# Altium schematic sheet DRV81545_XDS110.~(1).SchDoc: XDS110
size 431 x 279 mm; Date: Not shown in title block; ApprovedBy: Not shown in title block; CheckedBy: Not shown in title block; Author: Not shown in title block; CompanyName: Not shown in title block; DrawnBy: Mojtaba Afshar; Engineer: Not shown in title block; Organization: Not shown in title block; Address1: Not shown in title block; Address2: Not shown in title block; Address3: Not shown in title block; Address4: Not shown in title block; DocumentNumber: 2; Revision: Use project parameter SCH_Rev; SheetNumber: 1; SheetTotal: 5; PageSetup: Record=PageOptions¦CenterHorizontal=True¦CenterVertical=True¦PrintScale=1.00¦XCorrection=1.00¦YCorrection=1.00¦PrintKind=0¦BorderSize=5000000¦LeftOffset=0¦BottomOffset=0¦Orientation=2¦PaperLength=1000¦PaperWidth=1000¦Scale=100¦PaperSource=15¦PrintQuality=600¦MediaType=1¦DitherType=10¦PaperKind=Letter¦PrintScaleMode=1
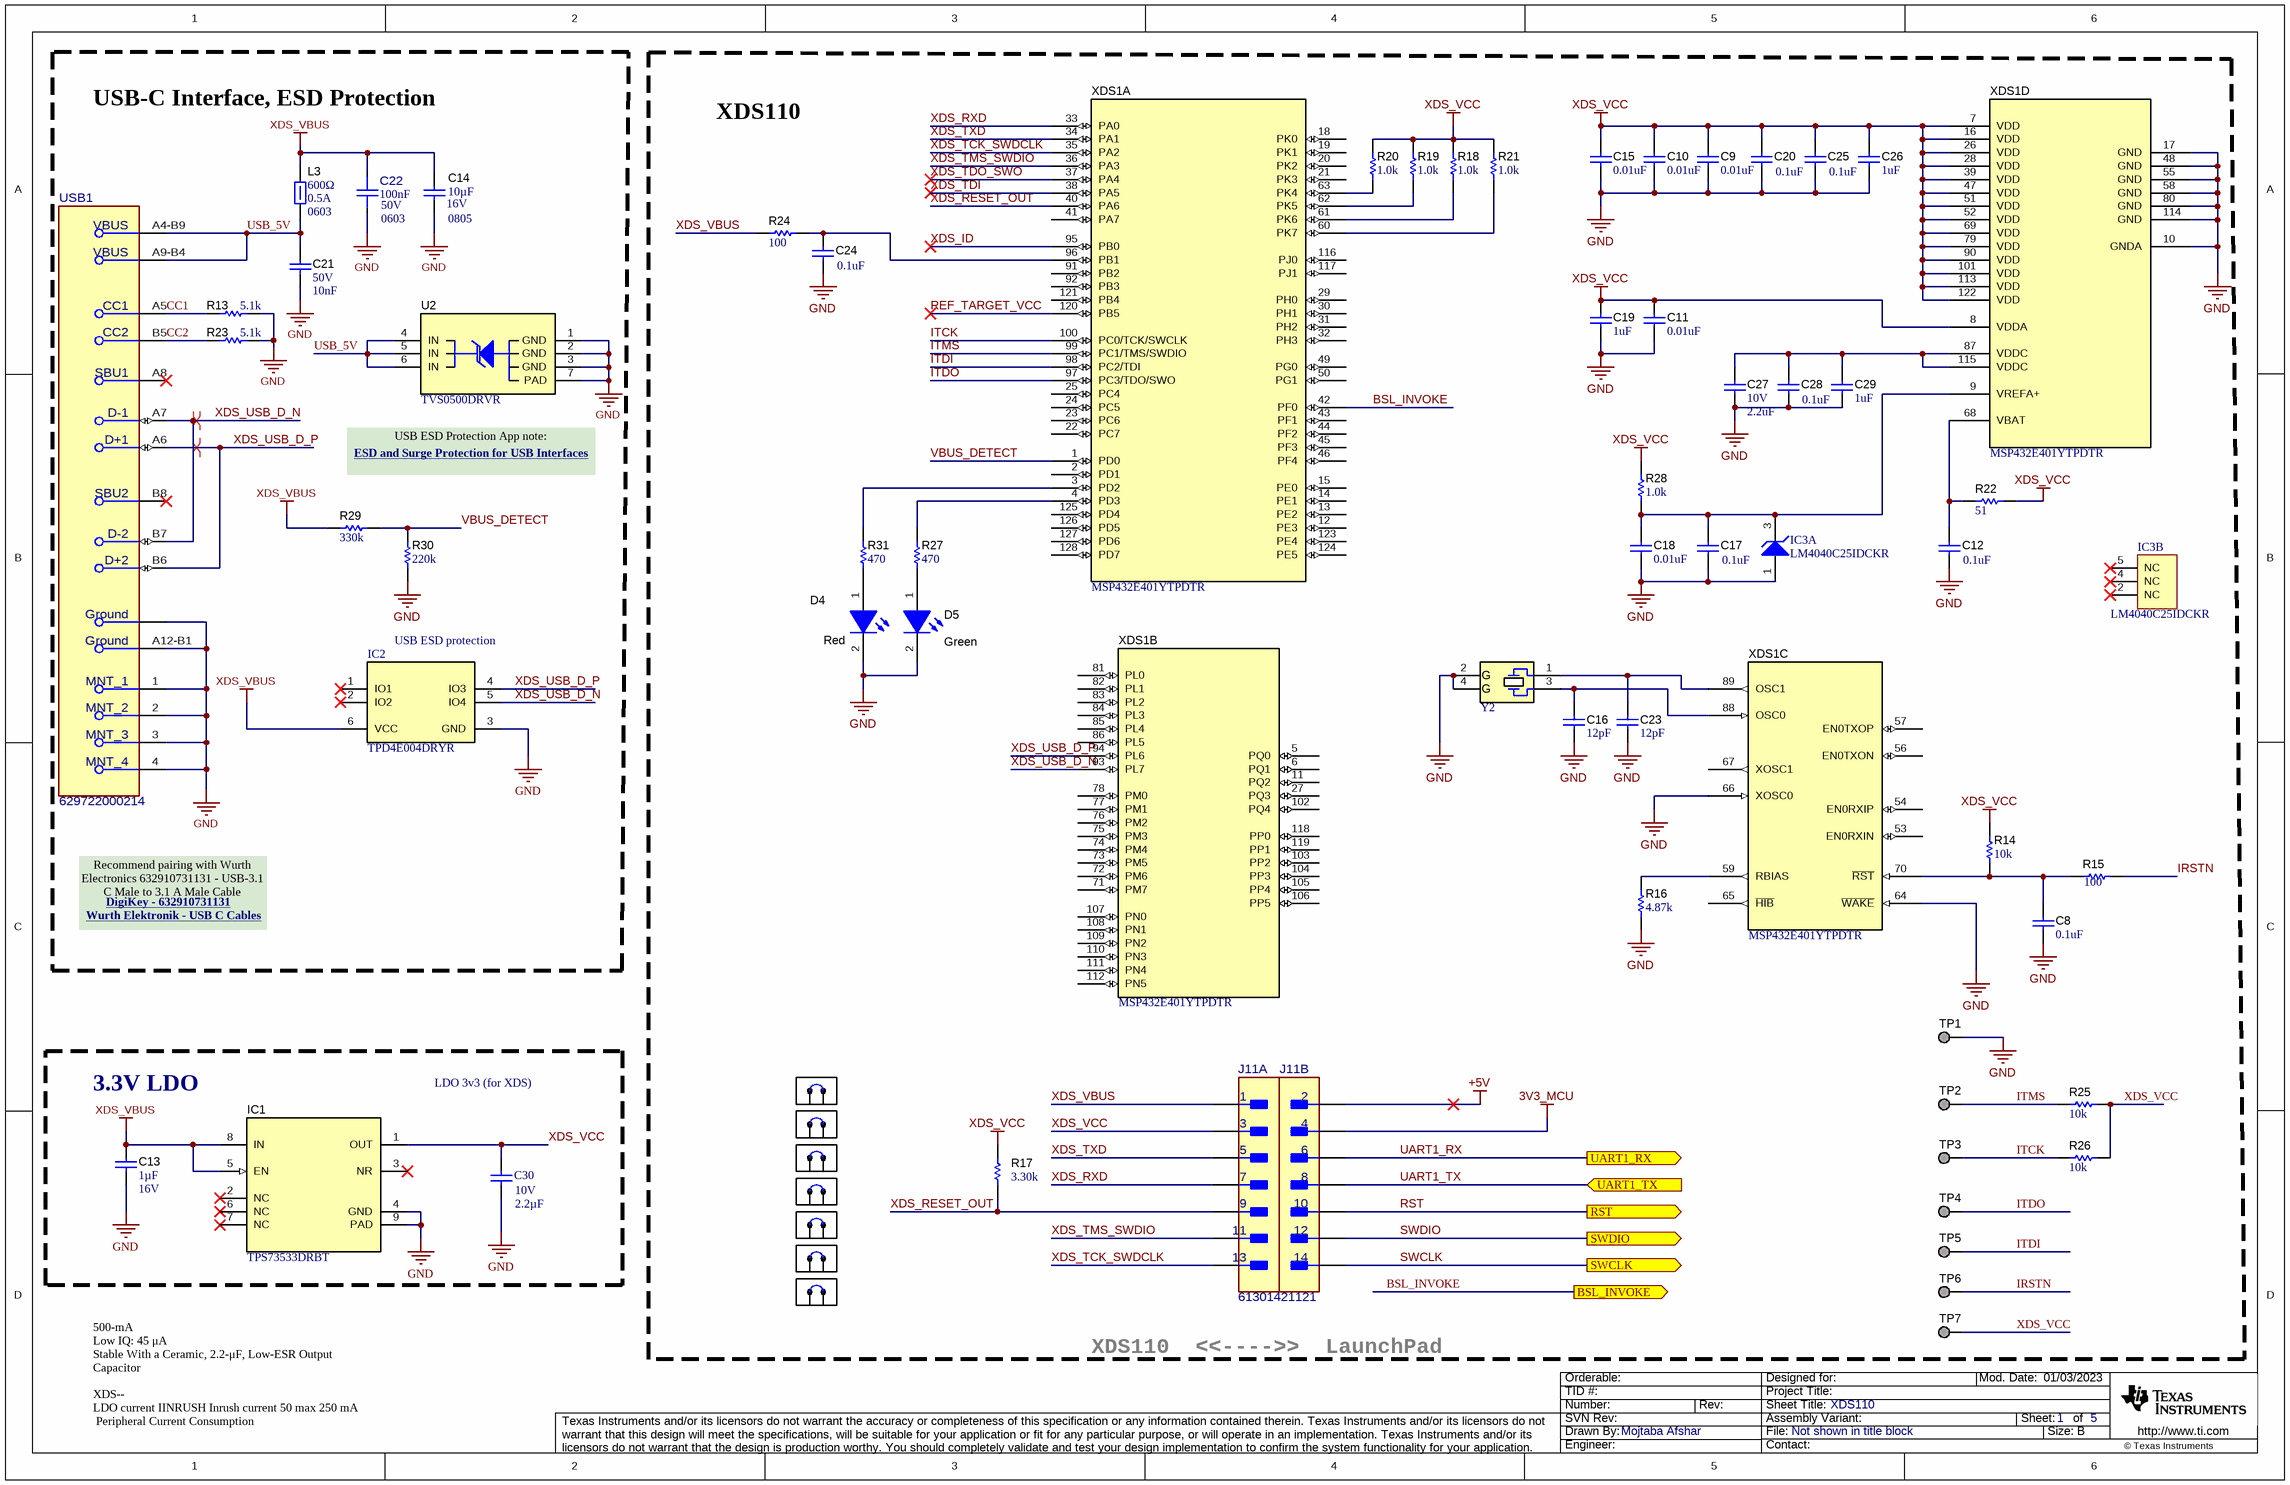
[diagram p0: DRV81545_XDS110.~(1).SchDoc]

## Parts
C8  ValueDisplayed: 0.1uF  [0402]  (hidden comment: GRM155R70J104KA01D)
C9  ValueDisplayed: 0.01uF  [0402]  (hidden comment: GRM155R71E103KA01D)
C10  ValueDisplayed: 0.01uF  [0402]  (hidden comment: GRM155R71E103KA01D)
C11  ValueDisplayed: 0.01uF  [0402]  (hidden comment: GRM155R71E103KA01D)
C12  ValueDisplayed: 0.1uF  [0402]  (hidden comment: GRM155R70J104KA01D)
C13  Cap_F: 1µF  VDC_V: 16V  [0603]  (hidden comment: 885012206052)
C14  PackageReference: 0805  VDC_V: 16V  ValueDisplayed: 10µF  [0805_150]  (hidden comment: 885012107014)
C15  ValueDisplayed: 0.01uF  [0402]  (hidden comment: GRM155R71E103KA01D)
C16  ValueDisplayed: 12pF  [0402]  (hidden comment: GRM1555C1H120JA01D)
C17  ValueDisplayed: 0.1uF  [0402]  (hidden comment: GRM155R70J104KA01D)
C18  ValueDisplayed: 0.01uF  [0402]  (hidden comment: GRM155R71E103KA01D)
C19  ValueDisplayed: 1uF  [0402]  (hidden comment: C1005X5R1E105K050BC)
C20  ValueDisplayed: 0.1uF  [0402]  (hidden comment: GRM155R70J104KA01D)
C21  VDC_V: 50V  Cap_F: 10nF  [0603]  (hidden comment: 885012206089)
C22  Cap_F: 100nF  PackageReference: 0603  VDC_V: 50V  [FP-885012206095_0603-MFG]  (hidden comment: 885012206095)
C23  ValueDisplayed: 12pF  [0402]  (hidden comment: GRM1555C1H120JA01D)
C24  ValueDisplayed: 0.1uF  [0402]  (hidden comment: GRM155R70J104KA01D)
C25  ValueDisplayed: 0.1uF  [0402]  (hidden comment: GRM155R70J104KA01D)
C26  ValueDisplayed: 1uF  [0402]  (hidden comment: C1005X5R1E105K050BC)
C27  VDC_V: 10V  ValueDisplayed: 2.2uF  [0603]  (hidden comment: C0603C225K8PACTU)
C28  ValueDisplayed: 0.1uF  [0402]  (hidden comment: GRM155R70J104KA01D)
C29  ValueDisplayed: 1uF  [0402]  (hidden comment: C1005X5R1E105K050BC)
C30  value 2.2µF  Rated Voltage (DC): 10V  [WCAP-CSGP_0603_L1.6W0.8H0.8_Reflow]  (hidden comment: 885012206027)
D4  value Red  [LED_LTST-C190_Red]  (hidden comment: LTST-C190KRKT)
D5  value Green  [LED_LTST-C190]  (hidden comment: LTST-C190GKT)
IC1  TPS73533DRBT  [DRB0008A]
IC2  TPD4E004DRYR  [DRY0006A]
IC3  LM4040C25IDCKR  [DCK0005A_N]  (parts A,B of 2)
J11  61301421121  [FP-61301421121_HDR14-MFG]  (parts A,B of 2)
L3  Value2: 0.5A  ValueDisplayed: 600Ω  [0603]  (hidden comment: 742863160)
R13  ValueDisplayed: 5.1k  [0603]  (hidden comment: RC0603JR-075K1L)
R14  ValueDisplayed: 10k  [0402]  (hidden comment: CRCW040210K0JNED)
R15  ValueDisplayed: 100  [0402]  (hidden comment: CRCW0402100RJNED)
R16  ValueDisplayed: 4.87k  [0402]  (hidden comment: CRCW04024K87FKED)
R17  ValueDisplayed: 3.30k  [0402]  (hidden comment: ERJ-2RKF3301X)
R18  ValueDisplayed: 1.0k  [0402]  (hidden comment: CRCW04021K00JNED)
R19  ValueDisplayed: 1.0k  [0402]  (hidden comment: CRCW04021K00JNED)
R20  ValueDisplayed: 1.0k  [0402]  (hidden comment: CRCW04021K00JNED)
R21  ValueDisplayed: 1.0k  [0402]  (hidden comment: CRCW04021K00JNED)
R22  ValueDisplayed: 51  [0402]  (hidden comment: CRCW040251R0JNED)
R23  ValueDisplayed: 5.1k  [0603]  (hidden comment: RC0603JR-075K1L)
R24  ValueDisplayed: 100  [0402]  (hidden comment: CRCW0402100RJNED)
R25  ValueDisplayed: 10k  [0402]  (hidden comment: CRCW040210K0JNED)
R26  ValueDisplayed: 10k  [0402]  (hidden comment: CRCW040210K0JNED)
R27  ValueDisplayed: 470  [0402]  (hidden comment: CRCW0402470RJNED)
R28  ValueDisplayed: 1.0k  [0402]  (hidden comment: CRCW04021K00JNED)
R29  ValueDisplayed: 330k  [0402]  (hidden comment: RC0402FR-07330KL)
R30  ValueDisplayed: 220k  [0402]  (hidden comment: RC0402FR-07220KL)
R31  ValueDisplayed: 470  [0402]  (hidden comment: CRCW0402470RJNED)
SH-J14  60900213421  [Wurth_60900213421]  (value not drawn)
SH-J15  60900213421  [Wurth_60900213421]  (value not drawn)
SH-J16  60900213421  [Wurth_60900213421]  (value not drawn)
SH-J17  60900213421  [Wurth_60900213421]  (value not drawn)
SH-J18  60900213421  [Wurth_60900213421]  (value not drawn)
SH-J19  60900213421  [Wurth_60900213421]  (value not drawn)
SH-J20  60900213421  [Wurth_60900213421]  (value not drawn)
TP1  TESTPOINT  [TP_SM_1MM]  (value not drawn)  (no BOM)
TP2  TESTPOINT  [TP_SM_1MM]  (value not drawn)  (no BOM)
TP3  TESTPOINT  [TP_SM_1MM]  (value not drawn)  (no BOM)
TP4  TESTPOINT  [TP_SM_1MM]  (value not drawn)  (no BOM)
TP5  TESTPOINT  [TP_SM_1MM]  (value not drawn)  (no BOM)
TP6  TESTPOINT  [TP_SM_1MM]  (value not drawn)  (no BOM)
TP7  TESTPOINT  [TP_SM_1MM]  (value not drawn)  (no BOM)
U2  TVS0500DRVR  [DRV0006A]
USB1  629722000214  [FP-629722000214_CONN_USB-MFG]
XDS1  MSP432E401YTPDTR  [PDT0128A]  (parts A,B,C,D of 4)
Y2  NX3225GA-16.000M-STD-CRG-1  [NDK_NX3225GA]  (value not drawn)

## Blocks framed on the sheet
USB-C Interface, ESD Protection: C14 C21 C22 IC2 L3 R13 R23 R29 R30 U2 USB1
XDS110: C8-C12 C15-C20 C23-C29 D4 D5 IC3 J11 R14-R22 R24-R28 R31 SH-J14-SH-J20 TP1-TP7 XDS1 Y2
3.3V LDO: C13 C30 IC1

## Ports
BSL_INVOKE (out), RST (out), SWCLK (out), SWDIO (out), UART1_RX (out), UART1_TX (in)

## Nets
3V3_MCU: J11.4
+5V: J11.2
GND: C8.2 C9.2 C10.2 C11.2 C12.2 C13.2 C14.2 C15.2 C16.2 C17.2 C18.2 C19.2 C20.2 C21.2 C22.2 C23.2 C24.2 C25.2 C26.2 C27.2 C28.2 C29.2 C30.1 D4.2(K) D5.2(K) IC1.4(GND) IC1.9(PAD) IC2.3(GND) IC3.1(ANODE) R13.2 R16.1 R23.2 R30.1 TP1.1 U2.1(GND) U2.2(GND) U2.3(GND) U2.7(PAD) USB1.1(MNT_1) USB1.2(MNT_2) USB1.3(MNT_3) USB1.4(MNT_4) USB1.A1-B12(Ground) USB1.A12-B1(Ground) XDS1.10(GNDA) XDS1.17(GND) XDS1.48(GND) XDS1.55(GND) XDS1.58(GND) XDS1.64(~{WAKE}) XDS1.66(XOSC0) XDS1.80(GND) XDS1.114(GND) Y2.2(GND) Y2.4(GND)
XDS_VBUS: C13.1 C14.1 C22.1 IC1.5(EN) IC1.8(IN) IC2.6(VCC) J11.1 L3.2 R24.1 R29.1
XDS_VCC: C9.1 C10.1 C11.1 C15.1 C19.1 C20.1 C25.1 C26.1 C30.2 IC1.1(OUT) J11.3 R14.2 R17.2 R18.2 R19.2 R20.2 R21.2 R22.2 R25.1 R26.1 R28.2 TP7.1 XDS1.7(VDD) XDS1.8(VDDA) XDS1.16(VDD) XDS1.26(VDD) XDS1.28(VDD) XDS1.39(VDD) XDS1.47(VDD) XDS1.51(VDD) XDS1.52(VDD) XDS1.69(VDD) XDS1.79(VDD) XDS1.90(VDD) XDS1.101(VDD) XDS1.113(VDD) XDS1.122(VDD)
BSL_INVOKE: XDS1.42(PF0) ; port BSL_INVOKE
CC1: R13.1 USB1.A5(CC1)
CC2: R23.1 USB1.B5(CC2)
IRSTN: R15.1 TP6.1
ITCK: R26.2 TP3.1 XDS1.100(PC0/TCK/SWCLK)
ITDI: TP5.1 XDS1.98(PC2/TDI)
ITDO: TP4.1 XDS1.97(PC3/TDO/SWO)
ITMS: R25.2 TP2.1 XDS1.99(PC1/TMS/SWDIO)
REF_TARGET_VCC: XDS1.120(PB5)
RST: J11.10 ; port RST
SWCLK: J11.14 ; port SWCLK
SWDIO: J11.12 ; port SWDIO
UART1_RX: J11.6 ; port UART1_RX
UART1_TX: J11.8 ; port UART1_TX
USB_5V: C21.1 L3.1 U2.4(IN) U2.5(IN) U2.6(IN) USB1.A4-B9(VBUS) USB1.A9-B4(VBUS)
VBUS_DETECT: R29.2 R30.2 XDS1.1(PD0)
XDS_ID: XDS1.95(PB0)
XDS_RESET_OUT: J11.9 R17.1 XDS1.40(PA6)
XDS_RXD: J11.7 XDS1.33(PA0)
XDS_TCK_SWDCLK: J11.13 XDS1.35(PA2)
XDS_TDI: XDS1.38(PA5)
XDS_TDO_SWO: XDS1.37(PA4)
XDS_TMS_SWDIO: J11.11 XDS1.36(PA3)
XDS_TXD: J11.5 XDS1.34(PA1)
XDS_USB_D_N: IC2.5(IO4) USB1.A7(D-1) USB1.B7(D-2) XDS1.93(PL7)
XDS_USB_D_P: IC2.4(IO3) USB1.A6(D+1) USB1.B6(D+2) XDS1.94(PL6)
NetC8_1: C8.1 R14.1 R15.2 XDS1.70(~{RST})
NetC12_1: C12.1 R22.1 XDS1.68(VBAT)
NetC16_1: C16.1 XDS1.88(OSC0) Y2.3
NetC17_1: C17.1 C18.1 IC3.3(CATHODE) R28.1 XDS1.9(VREFA+)
NetC23_1: C23.1 XDS1.89(OSC1) Y2.1
NetC24_1: C24.1 R24.2 XDS1.96(PB1)
NetC27_1: C27.1 C28.1 C29.1 XDS1.87(VDDC) XDS1.115(VDDC)
NetD4_1: D4.1(A) R31.1
NetD5_1: D5.1(A) R27.1
NetR16_2: R16.2 XDS1.59(RBIAS)
NetR18_1: R18.1 XDS1.61(PK6)
NetR19_1: R19.1 XDS1.62(PK5)
NetR20_1: R20.1 XDS1.63(PK4)
NetR21_1: R21.1 XDS1.60(PK7)
NetR27_2: R27.2 XDS1.4(PD3)
NetR31_2: R31.2 XDS1.3(PD2)

Not connected (* = marked no-connect by the designer): IC1 2(NC)* 3(NR)* 6(NC)* 7(NC)*; IC2 1(IO1)* 2(IO2)*; IC3 2(NC)* 4(NC)* 5(NC)*; USB1 A8(SBU1)* B8(SBU2)*; XDS1 2(PD1) 5(PQ0) 6(PQ1) 11(PQ2) 12(PE3) 13(PE2) 14(PE1) 15(PE0) 18(PK0) 19(PK1) 20(PK2) 21(PK3) 22(PC7) 23(PC6) 24(PC5) 25(PC4) 27(PQ3) 29(PH0) 30(PH1) 31(PH2) 32(PH3) 41(PA7) 43(PF1) 44(PF2) 45(PF3) 46(PF4) 49(PG0) 50(PG1) 53(EN0RXIN) 54(EN0RXIP) 56(EN0TXON) 57(EN0TXOP) 65(~{HIB}) 67(XOSC1) 71(PM7) 72(PM6) 73(PM5) 74(PM4) 75(PM3) 76(PM2) 77(PM1) 78(PM0) 81(PL0) 82(PL1) 83(PL2) 84(PL3) 85(PL4) 86(PL5) 91(PB2) 92(PB3) 102(PQ4) 103(PP2) 104(PP3) 105(PP4) 106(PP5) 107(PN0) 108(PN1) 109(PN2) 110(PN3) 111(PN4) 112(PN5) 116(PJ0) 117(PJ1) 118(PP0) 119(PP1) 121(PB4) 123(PE4) 124(PE5) 125(PD4) 126(PD5) 127(PD6) 128(PD7)

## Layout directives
differential pair: XDS_USB_D_N, XDS_USB_D_P

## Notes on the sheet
- USB ESD Protection App note:
- ESD and Surge Protection for USB Interfaces <https://www.ti.com/lit/an/slvaf82b/slvaf82b.pdf>
- (near IC2) USB ESD protection
- Recommend pairing with Wurth Electronics 632910731131 - USB-3.1 C Male to 3.1 A Male Cable
- Wurth Elektronik - USB C Cables <https://www.we-online.com/en/components/products/COM_3_1_CAB_ASSEMBLIES>
- DigiKey - 632910731131 <https://www.digikey.com/en/products/detail/w%C3%BCrth-elektronik/632910731131/5723517>
- LDO 3v3 (for XDS)
- XDS110  <<---->>  LaunchPad
- 500-mA
  Low IQ: 45 μA
  Stable With a Ceramic, 2.2-μF, Low-ESR Output
  Capacitor
  XDS--
  LDO current IINRUSH Inrush current 50 max 250 mA
  Peripheral Current Consumption
  M0 IVDD 100 mA
  m0IVss 100 mA
  m0 I IO 60 mA
  LEDs with 470 takes 3.5 maA
  IDDUSB 4mA
  IDDEMAC 2 mA
  IDDEMACPHY 30mA

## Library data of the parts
C8 C12 C17 C20 C24 C25 C28 = CMP-0006623-2: CAP, CERM, 0.1 uF, 6.3 V, +/- 10%, X7R, 0402; Manufacturer: MuRata; TaMin_C: -55°C; Polarized: N; SizeAreaWB_mm2: 3; Value1: Unknown; U/M: EA; Value: 0.1uF; TaMax_C: 125°C; SizeZ_mm: 0.6; SizeX_mm: 1; SizeY_mm: 0.5; Value2: 6.3V; Cap_F: 100nF; AEC Category: Q200
C9-C11 C15 C18 = CMP-0006658-2: CAP, CERM, 0.01 uF, 25 V, +/- 10%, X7R, 0402; Manufacturer: MuRata; TaMin_C: -55°C; Polarized: N; SizeAreaWB_mm2: 3; Value1: Unknown; U/M: EA; Value: 0.01uF; TaMax_C: 125°C; SizeZ_mm: 0.6; SizeX_mm: 1; SizeY_mm: 0.5; Value2: 25V; Cap_F: 10nF; AEC Category: Q200
C13 = CMP-0006831-4: CAP, CERM, 1 uF, 16 V, +/- 10%, X7R, 0603; Manufacturer: Wurth Elektronik; TaMin_C: -55°C; Polarized: N; SizeAreaWB_mm2: 4.68; Value1: Unknown; U/M: EA; Value: 1uF; TaMax_C: 125°C; SizeZ_mm: 1; SizeX_mm: 1.6; SizeY_mm: 0.8; SizeArea_mm2: 1.28; AEC Category: Q200
C14 = CMP-0078154-1: CAP, CERM, 10 µF, 16 V,+/- 20%, X5R, 0805; Manufacturer: Wurth Elektronik; TaMin_C: -55°C; Polarized: N; SizeAreaWB_mm2: 6.75; U/M: EA; Value: 10uF; TaMax_C: 85°C; SizeZ_mm: 1.5; SizeX_mm: 2; SizeY_mm: 1.25; SizeArea_mm2: 2.5; AEC Category: Q200
C16 C23 = CMP-0006415-2: CAP, CERM, 12 pF, 50 V, +/- 5%, C0G/NP0, 0402; Manufacturer: MuRata; TaMin_C: -55°C; Polarized: N; SizeAreaWB_mm2: 3; Value1: Unknown; U/M: EA; Value: 12pF; TaMax_C: 125°C; SizeZ_mm: 0.6; SizeX_mm: 1; SizeY_mm: 0.5; Value2: 50V; AEC Category: Q200
C19 C26 C29 = CMP-0006276-2: CAP, CERM, 1 uF, 25 V, +/- 10%, X5R, 0402; Manufacturer: TDK; TaMin_C: -55°C; Polarized: N; SizeAreaWB_mm2: 3; Value1: Unknown; U/M: EA; Value: 1uF; TaMax_C: 80°C; SizeZ_mm: 0.6; SizeX_mm: 1; SizeY_mm: 0.5; Value2: 25V; Cap_F: 1µF; AEC Category: Q200
C21 = CMP-0750039-1: CAP, CERM, 0.01 µF, 50 V,+/- 10%, X7R, 0603; Manufacturer: Wurth Elektronik; Polarized: N; AEC Category: Q200; TaMax_C: 125°C; SizeAreaWB_mm2: 4.68; Value: 0.01uF; SizeArea_mm2: 1.28; SizeY_mm: 0.8; SizeZ_mm: 1; ValueDisplayed: 0.01µF; SizeX_mm: 1.6; U/M: EA; TaMin_C: -55°C
C22 = CMP-0049204-1: 0.1 µF ±10% 50V Ceramic Capacitor X7R 0603 (1608 Metric); Manufacturer: Wurth; AEC Qualified: No; SizeZ_mm: 0.87mm; TempCo: 15%; Value: 100nF
C27 = CMP-0006906-5: CAP, CERM, 2.2 uF, 10 V, +/- 10%, X5R, 0603; Manufacturer: Kemet; TaMin_C: -55°C; Polarized: N; SizeAreaWB_mm2: 4.68; Value1: Unknown; U/M: EA; Value: 2.2uF; TaMax_C: 85°C; SizeZ_mm: 1; SizeX_mm: 1.6; SizeY_mm: 0.8; SizeArea_mm2: 1.28; Cap_F: 2.2µF; AEC Category: Q200
C30 = CMP-0119330-1: WCAP-CSGP Multilayer Ceramic Chip Capacitor, General Purpose, size 0603, X7R, 2.2µF, 10VDC; Manufacturer: Wurth Elektronik; Capacitance Tolerance: +/-10%; Case/Size Code: 0603; Dissipation Factor: 10%; Insulation Resistance: 0.02GOhm; Technical Reference: X7R0603225K010DFCT10000
D4 = CMP-0078131-2: LED, Red, SMD; Manufacturer: Lite-On; Type: AlInGaP; Ir_A: 10µA; Angle: 130; Power_TotalModule: 62.5mW; Value2: 2V; Green_Lifecycle: Not Set; Io_A: 20mA; Value1: .0625W; Green_REACh: Incomplete; Vr_V: 5V
D5 = CMP-0002827-3: LED, Green, SMD; Manufacturer: Lite-On; Power_TotalModule: 100mW; Value2: 2.1V; Io_A: 20mA; Value1: 0.1W
IC1 = CMP-0036329-3: 500mA, Adjustable, Low Quiescent Current, Low-Noise, High-PSRR, Single-Output LDO Regulator, DRB0008A (VSON-8); Manufacturer: Texas Instruments; AEC Category: Q200; Vout Adj(Max)(V): 3.3; Vdo(Typ)(mV): 280; SizeY_mm: 3.0; Vin(Max)(V): 6.5; Accuracy(%): 2; Vin(Min)(V): 2.7; SizeAreaWB_mm2: 16.0; SizeZ_mm: 1.0; AEC Qualified: N; SizeArea_mm2: 9.0; Iout(Max)(A): 0.5; Rating: Catalog; Iq(Typ)(mA): 0.04; CompType: IC
IC2 = CMP-0043115-3: 4-Channel ESD Protection Array for High-Speed Data Interfaces, DRY0006A (USON-6); Manufacturer: Texas Instruments; IO Leakage Current(nA): 1; USB High Speed: TRUE; IO Capacitance(Typ)(pF): 1.6; Eco-Plan: Green (RoHS & no Sb/Br); IEC 61000-4-2 Contact(+/- kV): 8; Breakdown Voltage(Min)(V): 6; IEC 61000-4-2 Air-Gap(+/- kV): 12; AEC Category: Q200; AEC Qualified: N; CompType: IC; Rating: Catalog; SizeArea_mm2: 1.45; SizeAreaWB_mm2: 4.9; SizeX_mm: 1.0; SizeZ_mm: 0.6
IC3 = CMP-0032790-2: Precision Micropower Shunt Voltage Reference, 0.5% accuracy, 2.5 V, 15 ppm / degC, 15 mA, -40 to 85 degC, 5-pin SC70 (DCK), Green (RoHS & no Sb/Br); Manufacturer: Texas Instruments; Min Iz for Regulation(uA): 75; Temp Coeff(Max)(ppm/ degree C): 100; VO(V): 2.5; Temp Coeff(Typ)(ppm/ degree C): 15; Rating: Catalog; Initial Accuracy @ 25/deg C(%): 0.5; AEC Category: Q200; AEC Qualified: N; CompType: IC; SizeAreaWB_mm2: 9.3; SizeArea_mm2: 4.2; SizeX_mm: 2.1; SizeY_mm: 2.0; SizeZ_mm: 1.1
J11 = CMP-0097334-1: Connector Header Through Hole 14 position 0.100" (2.54mm); Manufacturer: Wurth Electronics; AEC Qualified: No; Conn Gender: Male; Current_A: 3A; Voltage_V: 250V; ContactFinish: Gold; Row_Count: 2; SizeZ_mm: 8.89mm; Conn Orientation: Straight
L3 = CMP-0003267-2: Ferrite Bead, 600 ohm @ 100 MHz, 0.5 A, 0603; Manufacturer: Wurth Elektronik; Ztyp@1GHz_Ohm: 997.006; ZTyp@100MHz_Ohm: 600; SizeAreaWB_mm2: 4.68; DCR_ohm: 3.5d; Value1: 0.35 ohm; Value: 600 ohm; Imax_A: 5dA; SizeZ_mm: 1; SizeX_mm: 1.6; SizeY_mm: 0.8; SizeArea_mm2: 1.28
R13 R23 = CMP-0025932-5: RES, 5.1 k, 5%, 0.1 W, 0603; Manufacturer: Yageo; Power_W: 100mW; TempCo: 100 ppm/C; Value_Code: 5k10; Value: 5.1k; EIA_Code: E24; SizeX_mm: 1.6; SizeY_mm: 0.8; SizeZ_mm: 1; Value2: 0.1W; SizeArea_mm2: 1.28; AEC Qualified: N; VDC_V: 75V; AEC Category: Q200; SizeAreaWB_mm2: 4.68
R14 R25 R26 = CMP-0026825-5: RES, 10 k, 5%, 0.063 W, AEC-Q200 Grade 0, 0402; Manufacturer: Vishay-Dale; Power_W: 63mW; TempCo: 200 ppm/C; Value_Code: 10k0; Value: 10k; EIA_Code: E24; SizeX_mm: 1; SizeY_mm: 0.5; SizeZ_mm: 0.6; Value2: 0.063W; AEC Qualified: Y; VDC_V: 50V; AEC Category: Q200; AEC Grade: 0
R15 R24 = CMP-0026824-3: RES, 100, 5%, 0.063 W, AEC-Q200 Grade 0, 0402; Manufacturer: Vishay-Dale; Power_W: 63mW; TempCo: 200 ppm/C; Value_Code: 100R; Value: 100; EIA_Code: E24; SizeX_mm: 1; SizeY_mm: 0.5; SizeZ_mm: 0.6; Value2: 0.063W; AEC Qualified: Y; VDC_V: 50V; AEC Category: Q200; AEC Grade: 0
R16 = CMP-0026413-2: RES, 4.87 k, 1%, 0.063 W, AEC-Q200 Grade 0, 0402; Manufacturer: Vishay-Dale; Power_W: 63mW; TempCo: 100 ppm/C; Value_Code: 4k87; Value: 4.87k; EIA_Code: E96; SizeX_mm: 1; SizeY_mm: 0.5; SizeZ_mm: 0.6; Value2: 0.063W; AEC Qualified: Y; VDC_V: 50V; AEC Category: Q200; AEC Grade: 0
R17 = CMP-0026695-1: RES, 3.30 k, 1%, 0.1 W, AEC-Q200 Grade 0, 0402; Manufacturer: Panasonic; Power_W: 100mW; TempCo: 100 ppm/C; Value_Code: 3k30; U/M: EA; Value: 3.30k; Res_ohm: 3.3k; SizeX_mm: 1; SizeY_mm: 0.5; SizeZ_mm: 0.6; Value2: 0.1W; AEC Qualified: Y; VDC_V: 50V; AEC Grade: 0; AEC Category: Q200
R18-R21 R28 = CMP-0026852-3: RES, 1.0 k, 5%, 0.063 W, AEC-Q200 Grade 0, 0402; Manufacturer: Vishay-Dale; Power_W: 63mW; TempCo: 200 ppm/C; Value_Code: 1k00; Value: 1.0k; EIA_Code: E24; Res_ohm: 1k; SizeX_mm: 1; SizeY_mm: 0.5; SizeZ_mm: 0.6; Value2: 0.063W; AEC Qualified: Y; VDC_V: 50V; AEC Category: Q200; AEC Grade: 0
R22 = CMP-0026946-3: RES, 51, 5%, 0.063 W, AEC-Q200 Grade 0, 0402; Manufacturer: Vishay-Dale; Power_W: 63mW; TempCo: 200 ppm/C; Value_Code: 51R0; Value: 51; EIA_Code: E24; SizeX_mm: 1; SizeY_mm: 0.5; SizeZ_mm: 0.6; Value2: 0.063W; AEC Qualified: Y; VDC_V: 50V; AEC Category: Q200; AEC Grade: 0
R27 R31 = CMP-0026934-3: RES, 470, 5%, 0.063 W, AEC-Q200 Grade 0, 0402; Manufacturer: Vishay-Dale; Power_W: 63mW; TempCo: 200 ppm/C; Value_Code: 470R; Value: 470; EIA_Code: E24; SizeX_mm: 1; SizeY_mm: 0.5; SizeZ_mm: 0.6; Value2: 0.063W; AEC Qualified: Y; VDC_V: 50V; AEC Category: Q200; AEC Grade: 0
R29 = CMP-0026731-1: RES, 330 k, 1%, 0.0625 W, 0402; Manufacturer: Yageo America; Power_W: 62.5mW; TempCo: 100 ppm/C; U/M: EA; Value: 330k; SizeX_mm: 1; SizeY_mm: 0.5; SizeZ_mm: 0.6; AEC Qualified: N; VDC_V: 50V; AEC Category: Q200
R30 = CMP-0026728-1: RES, 220 k, 1%, 0.0625 W, 0402; Manufacturer: Yageo America; Power_W: 62.5mW; TempCo: 100 ppm/C; U/M: EA; Value: 220k; SizeX_mm: 1; SizeY_mm: 0.5; SizeZ_mm: 0.6; AEC Qualified: N; VDC_V: 50V; AEC Category: Q200
SH-J14-SH-J20 = CMP-0003761-2: Shunt, 2.54mm, Gold, Black; Manufacturer: Wurth Elektronik
TP1-TP7 = CMP-0003825-1: 1mm Test Point, SMT; Manufacturer: Any
U2 = CMP-0077837-1: 5-V Precision Surge Protection Clamp, DRV0006A (WSON-6); Alternate Manufacturer: Texas Instruments; SizeAreaWB_mm2: 9.0; SizeZ_mm: 0.8; SizeX_mm: 2.0; SizeArea_mm2: 4.0; CompType: IC; AEC Qualified: N; AEC Category: Q200
USB1 = CMP-0095999-2: Conenctor USB 2.0 Type C Horizontal SMT; Manufacturer: Wurth Electronics; Current_A: 5A; ContactFinish: Gold,Nickel; AEC Qualified: No; Shrouded: true; Voltage_V: 20V; SizeZ_mm: 3.51mm; Usb Standard: USB 2.0; Is Female: yes
XDS1 = CMP-0077954-1: MSP432E401YTPDT, PDT0128A (TQFP-128); Alternate Manufacturer: Texas Instruments; SizeAreaWB_mm2: 324; SizeZ_mm: 1.2; SizeX_mm: 16; SizeArea_mm2: 256; CompType: IC; AEC Qualified: N; AEC Category: Q200
Y2 = CMP-0004635-3: Crystal, 16 MHz, 8pF, SMD; Manufacturer: NDK; TaMax_C: 70°C; TaMin_C: -10°C; Frequency Stability: +/-30ppm; Frequency_Fixed: 16MHz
